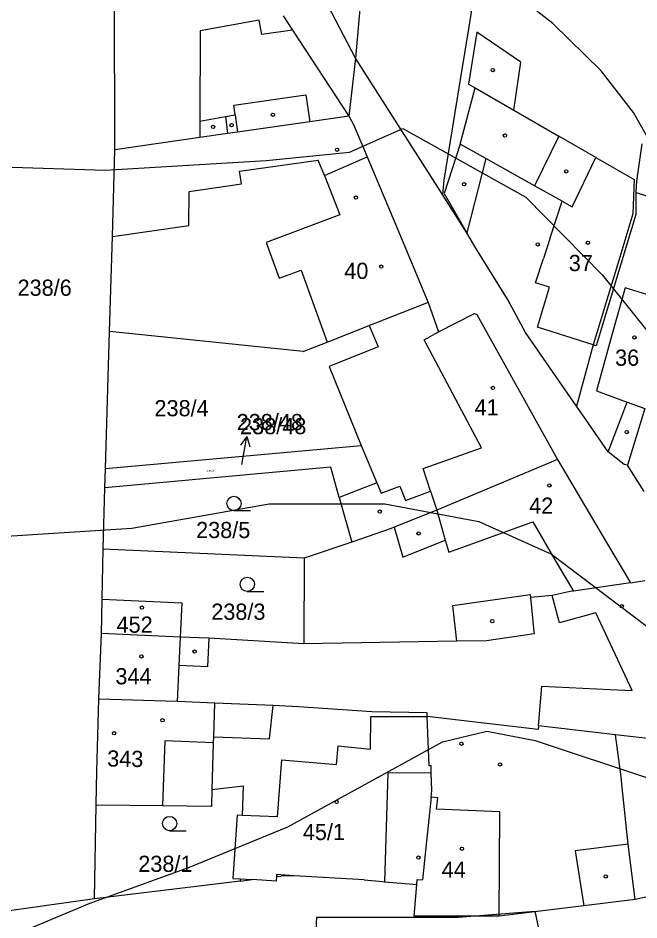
# Model space of a CAD drawing. Extents: x -555860 to -552701, y -1187050 to -1182291.
# Drawn here: x -554496.6 to -554431.4, y -1184380.5 to -1184285.9 of the extents above; entities that cross this region are included whole.
import ezdxf

# ---------------------------------------------------------------- set-up
doc = ezdxf.new("R2010")
doc.units = 0
for name, color, linetype in [('CYKLISTI_stav', 7, 'Continuous'), ('LEG_2b', 7, 'Continuous'), ('Level 16', 7, 'Continuous'), ('Level 25', 7, 'Continuous'), ('Level 40', 7, 'Continuous'), ('Level 41', 7, 'Continuous'), ('navrh_BV', 7, 'Continuous'), ('stav_BV', 7, 'Continuous')]:
    doc.layers.add(name, color=color, linetype=linetype)

msp = doc.modelspace()

# ---------------------------------------------------------------- linework, layer by layer
at = {"layer": 'CYKLISTI_stav'}
for p, q in [((-554471.28, -1184286.15), (-554477.48, -1184287.27)), ((-554471.01, -1184287.65), (-554471.28, -1184286.15)), ((-554477.48, -1184287.27), (-554477.49, -1184296.75)), ((-554467.77, -1184287.2), (-554471.01, -1184287.65)), ((-554448.44, -1184287.41), (-554449.31, -1184292.87)), ((-554443.8, -1184290.55), (-554448.44, -1184287.41)), ((-554444.56, -1184295.6), (-554443.8, -1184290.55)), ((-554449.31, -1184292.87), (-554448.62, -1184293.26)), ((-554473.94, -1184295.08), (-554466.36, -1184293.99)), ((-554466.36, -1184293.99), (-554465.96, -1184296.81)), ((-554450.19, -1184299.16), (-554448.62, -1184293.26)), ((-554448.62, -1184293.26), (-554444.56, -1184295.6)), ((-554473.79, -1184296.07), (-554473.94, -1184295.08)), ((-554474.79, -1184296.25), (-554473.79, -1184296.07)), ((-554473.79, -1184296.07), (-554473.53, -1184297.9)), ((-554444.56, -1184295.6), (-554439.82, -1184298.33)), ((-554477.49, -1184296.75), (-554474.79, -1184296.25)), ((-554477.49, -1184296.75), (-554477.49, -1184298.47)), ((-554474.79, -1184296.25), (-554474.58, -1184298.05)), ((-554439.82, -1184298.33), (-554442.36, -1184303.54)), ((-554435.93, -1184300.57), (-554439.82, -1184298.33)), ((-554450.19, -1184299.16), (-554451.87, -1184304.34)), ((-554447.5, -1184300.67), (-554450.19, -1184299.16)), ((-554464.43, -1184302.46), (-554459.94, -1184300.5)), ((-554447.5, -1184300.67), (-554449.49, -1184308.45)), ((-554442.36, -1184303.54), (-554447.5, -1184300.67)), ((-554438.44, -1184305.74), (-554435.93, -1184300.57)), ((-554435.93, -1184300.57), (-554431.91, -1184302.88)), ((-554464.43, -1184302.46), (-554465.07, -1184300.83)), ((-554439.48, -1184305.15), (-554442.36, -1184303.54)), ((-554431.91, -1184302.88), (-554432.05, -1184306.45)), ((-554451.87, -1184304.34), (-554449.49, -1184308.45)), ((-554440.74, -1184309), (-554439.48, -1184305.15)), ((-554439.48, -1184305.15), (-554438.44, -1184305.74)), ((-554432.05, -1184306.45), (-554433.43, -1184311.02)), ((-554440.74, -1184309), (-554441.44, -1184311.15)), ((-554442.26, -1184313.69), (-554441.44, -1184311.15)), ((-554433.43, -1184311.02), (-554436.21, -1184320.22)), ((-554440.81, -1184314.16), (-554442.26, -1184313.69)), ((-554442.07, -1184318.34), (-554440.81, -1184314.16)), ((-554432.86, -1184314.23), (-554434.23, -1184319.07)), ((-554427.82, -1184315.79), (-554432.86, -1184314.23)), ((-554436.21, -1184320.22), (-554442.07, -1184318.34)), ((-554453.94, -1184319.7), (-554452.44, -1184318.85)), ((-554447.95, -1184331.01), (-554453.94, -1184319.7)), ((-554434.23, -1184319.07), (-554435.88, -1184325.02)), ((-554435.88, -1184325.02), (-554432.65, -1184326.21)), ((-554434.64, -1184331.45), (-554432.65, -1184326.21)), ((-554432.65, -1184326.21), (-554430.81, -1184326.89)), ((-554454.06, -1184333.19), (-554447.95, -1184331.01)), ((-554453.29, -1184335.57), (-554454.06, -1184333.19)), ((-554458.92, -1184334.68), (-554458.46, -1184335.77)), ((-554458.46, -1184335.77), (-554456.51, -1184335.02)), ((-554456.51, -1184335.02), (-554455.93, -1184336.54)), ((-554455.93, -1184336.54), (-554453.29, -1184335.57)), ((-554453.29, -1184335.57), (-554452.64, -1184337.57)), ((-554452.64, -1184337.57), (-554451.74, -1184340.71)), ((-554457.09, -1184339.35), (-554456.2, -1184342.49)), ((-554451.38, -1184341.97), (-554442.56, -1184338.79)), ((-554442.56, -1184338.79), (-554440.23, -1184342.76)), ((-554456.2, -1184342.49), (-554451.74, -1184340.71)), ((-554451.74, -1184340.71), (-554451.38, -1184341.97)), ((-554440.23, -1184342.76), (-554438.3, -1184346.04)), ((-554450.96, -1184347.57), (-554442.84, -1184346.41)), ((-554442.84, -1184346.41), (-554442.81, -1184346.73)), ((-554439.76, -1184349.39), (-554440.52, -1184346.51)), ((-554450.54, -1184351.28), (-554450.96, -1184347.57)), ((-554435.93, -1184348.32), (-554439.76, -1184349.39)), ((-554434.63, -1184351.09), (-554435.93, -1184348.32)), ((-554479.55, -1184350.86), (-554479.69, -1184353.84)), ((-554432.13, -1184356.46), (-554434.63, -1184351.09)), ((-554441.97, -1184360.18), (-554441.61, -1184356.03)), ((-554441.61, -1184356.03), (-554434.44, -1184356.35)), ((-554434.44, -1184356.35), (-554432.13, -1184356.46)), ((-554470.2, -1184361.56), (-554469.81, -1184358.06)), ((-554459.55, -1184359.2), (-554453.65, -1184359.21)), ((-554476.03, -1184361.35), (-554470.2, -1184361.56)), ((-554481.18, -1184361.76), (-554481.4, -1184368.55)), ((-554476.05, -1184361.96), (-554481.18, -1184361.76)), ((-554469.35, -1184369.71), (-554468.88, -1184363.76)), ((-554457.77, -1184365.12), (-554458.13, -1184376.53)), ((-554457.77, -1184365.12), (-554453.21, -1184365.09)), ((-554452.53, -1184367.72), (-554453.23, -1184367.65)), ((-554452.66, -1184368.91), (-554452.53, -1184367.72)), ((-554446.02, -1184369.2), (-554452.66, -1184368.91)), ((-554469.35, -1184369.71), (-554473.05, -1184369.57)), ((-554446.1, -1184380.14), (-554446.02, -1184369.2)), ((-554432.55, -1184372.58), (-554438.11, -1184373.31)), ((-554438.11, -1184373.31), (-554437.2, -1184379.05)), ((-554473.26, -1184376.23), (-554472, -1184376.31))]:
    msp.add_line(p, q, dxfattribs=at)
for points in [[(-554486.68, -1184308.84), (-554478.67, -1184307.68), (-554478.61, -1184304.12), (-554473.14, -1184303.33), (-554473.33, -1184302), (-554465.07, -1184300.83)], [(-554464.43, -1184302.46), (-554462.81, -1184306.58), (-554470.54, -1184309.47), (-554469.19, -1184313.22), (-554466.88, -1184312.39), (-554464.14, -1184319.92)], [(-554468.88, -1184363.76), (-554463.15, -1184364.25), (-554462.98, -1184362.28), (-554459.6, -1184362.63), (-554459.55, -1184359.2)], [(-554467.63, -1184375.9), (-554469.46, -1184375.76), (-554469.47, -1184376)]]:
    msp.add_lwpolyline(points, dxfattribs=at)
at = {"layer": 'Level 16'}
for p, q in [((-554472.558, -1184329.826), (-554473.228, -1184330.722)), ((-554473.09, -1184332.779), (-554472.558, -1184329.826)), ((-554472.558, -1184329.826), (-554472.243, -1184330.899))]:
    msp.add_line(p, q, dxfattribs=at)
at = {"layer": 'Level 25'}
for p, q in [((-554473.922, -1184337.6), (-554472.172, -1184337.6)), ((-554472.522, -1184346.08), (-554470.772, -1184346.08)), ((-554480.672, -1184371.18), (-554478.922, -1184371.18))]:
    msp.add_line(p, q, dxfattribs=at)
for centre, radius in [((-554446.767, -1184291.389), 0.175), ((-554469.827, -1184296.069), 0.175), ((-554474.167, -1184297.149), 0.175), ((-554476.107, -1184297.349), 0.175), ((-554445.477, -1184298.259), 0.175), ((-554463.097, -1184299.749), 0.175), ((-554439.037, -1184302.009), 0.175), ((-554449.767, -1184303.369), 0.175), ((-554461.117, -1184304.759), 0.175), ((-554436.767, -1184309.499), 0.175), ((-554442.037, -1184309.669), 0.175), ((-554458.457, -1184311.999), 0.175), ((-554431.897, -1184319.429), 0.175), ((-554446.737, -1184324.729), 0.175), ((-554432.697, -1184329.359), 0.175), ((-554440.807, -1184334.949), 0.175), ((-554473.922, -1184336.85), 0.75), ((-554458.617, -1184337.699), 0.175), ((-554454.547, -1184339.999), 0.175), ((-554472.522, -1184345.33), 0.75), ((-554483.577, -1184347.779), 0.175), ((-554433.227, -1184347.629), 0.175), ((-554446.817, -1184349.199), 0.175), ((-554483.627, -1184352.889), 0.175), ((-554478.057, -1184352.389), 0.175), ((-554481.417, -1184359.599), 0.175), ((-554486.507, -1184360.959), 0.175), ((-554450.047, -1184362.059), 0.175), ((-554445.997, -1184364.219), 0.175), ((-554463.147, -1184368.169), 0.175), ((-554480.672, -1184370.43), 0.75), ((-554449.987, -1184373.079), 0.175), ((-554454.557, -1184374.009), 0.175), ((-554434.897, -1184375.969), 0.175)]:
    msp.add_circle(centre, radius, dxfattribs=at)
at = {"layer": 'Level 40'}
msp.add_lwpolyline([(-554517.787, -1184390.832), (-554489.12, -1184378.802), (-554478.588, -1184374.99), (-554468.255, -1184370.76), (-554452.027, -1184361.871), (-554447.37, -1184360.74), (-554442.29, -1184361.728), (-554418.197, -1184369.738), (-554409.458, -1184366.376), (-554396.338, -1184363.41), (-554380.817, -1184362.722), (-554365.423, -1184363.422), (-554347.817, -1184363.408), (-554330.133, -1184359.878), (-554319.19, -1184353.342), (-554303.762, -1184342.476), (-554293.19, -1184332.553), (-554285.468, -1184327.774)], dxfattribs=at)
at = {"layer": 'Level 41'}
for points in [[(-554293.988, -1184268.716), (-554293.412, -1184281.01), (-554294.964, -1184300.484), (-554298.492, -1184313.749), (-554303.996, -1184324.052), (-554309.076, -1184329.836), (-554316.414, -1184335.34), (-554324.881, -1184337.598), (-554333.348, -1184337.456), (-554340.404, -1184336.47), (-554371.45, -1184329.836), (-554394.028, -1184326.874), (-554403.906, -1184324.475), (-554409.551, -1184322.216), (-554417.453, -1184316.854), (-554422.533, -1184311.492), (-554425.356, -1184307.54), (-554431.988, -1184295.828), (-554435.375, -1184291.453), (-554440.455, -1184286.513), (-554452.732, -1184276.919), (-554465.01, -1184266.053), (-554485.983, -1184245.539), (-554497.733, -1184248.25)], [(-554497.187, -1184301.561), (-554487.447, -1184301.896), (-554470.521, -1184300.888), (-554461.782, -1184299.992), (-554456.18, -1184297.527), (-554443.277, -1184304.718), (-554435.234, -1184312.904), (-554426.061, -1184324.334), (-554416.042, -1184332.094), (-554407.011, -1184336.893), (-554400.237, -1184339.432), (-554388.948, -1184342.538), (-554357.338, -1184345.641), (-554338.872, -1184346.657), (-554323.635, -1184345.314), (-554313.551, -1184341.055), (-554305.26, -1184335.453), (-554299.21, -1184330.076), (-554292.935, -1184321.785), (-554278.313, -1184297.803)], [(-554498.307, -1184340.326), (-554484.625, -1184339.433), (-554470.231, -1184336.893), (-554458.095, -1184336.893), (-554448.217, -1184338.726), (-554440.606, -1184342.176), (-554427.833, -1184351.812), (-554420.886, -1184348.45), (-554411.251, -1184350.242), (-554403.58, -1184350.68), (-554376.674, -1184353.773), (-554345.212, -1184355.026), (-554329.432, -1184353.226), (-554307.277, -1184342.401), (-554296.788, -1184332.229)], [(-554465.587, -1184387.182), (-554465.231, -1184380.243), (-554450.389, -1184380.254), (-554442.35, -1184379.631), (-554441.049, -1184385.742)]]:
    msp.add_lwpolyline(points, dxfattribs=at)
at = {"layer": 'navrh_BV'}
for p, q in [((-554461.16, -1184290.15), (-554471.93, -1184269.33)), ((-554459.52, -1184271.8), (-554461.16, -1184290.15)), ((-554486.41, -1184299.76), (-554486.48, -1184276.68)), ((-554447.92, -1184278.57), (-554449.27, -1184286.85)), ((-554468.76, -1184285.7), (-554467.77, -1184287.2)), ((-554467.77, -1184287.2), (-554461.85, -1184296.22)), ((-554449.27, -1184286.85), (-554450.17, -1184292.38)), ((-554461.16, -1184290.15), (-554461.85, -1184296.22)), ((-554452.02, -1184304.43), (-554461.16, -1184290.15)), ((-554450.31, -1184293.25), (-554451.89, -1184302.93)), ((-554450.17, -1184292.38), (-554450.31, -1184293.25)), ((-554465.96, -1184296.81), (-554473.53, -1184297.9)), ((-554461.85, -1184296.22), (-554465.96, -1184296.81)), ((-554461.85, -1184296.22), (-554461.37, -1184297.1)), ((-554473.53, -1184297.9), (-554474.58, -1184298.05)), ((-554461.37, -1184297.1), (-554459.94, -1184300.5)), ((-554477.49, -1184298.47), (-554486.41, -1184299.76)), ((-554474.58, -1184298.05), (-554477.49, -1184298.47)), ((-554486.68, -1184308.84), (-554486.41, -1184299.76)), ((-554431.11, -1184299.13), (-554431.66, -1184303.03)), ((-554459.94, -1184300.5), (-554456.98, -1184307.56)), ((-554451.89, -1184302.93), (-554452.02, -1184304.43)), ((-554431.66, -1184303.03), (-554431.75, -1184304.22)), ((-554449.49, -1184308.45), (-554452.02, -1184304.43)), ((-554431.75, -1184304.22), (-554431.76, -1184306.54)), ((-554431.75, -1184304.22), (-554425.65, -1184306.07)), ((-554431.76, -1184306.54), (-554435.92, -1184320.31)), ((-554456.98, -1184307.56), (-554453.52, -1184315.77)), ((-554486.97, -1184318.81), (-554486.68, -1184308.84)), ((-554448.55, -1184310.07), (-554449.49, -1184308.45)), ((-554445.21, -1184315.42), (-554448.55, -1184310.07)), ((-554453.52, -1184315.77), (-554459.08, -1184317.93)), ((-554453.52, -1184315.77), (-554452.44, -1184318.85)), ((-554443.31, -1184318.91), (-554445.21, -1184315.42)), ((-554452.44, -1184318.85), (-554448.67, -1184316.93)), ((-554448.67, -1184316.93), (-554448.42, -1184317.03)), ((-554448.42, -1184317.03), (-554439.96, -1184332.25)), ((-554464.14, -1184319.92), (-554459.73, -1184318.19)), ((-554459.08, -1184317.93), (-554459.73, -1184318.19)), ((-554459.73, -1184318.19), (-554458.78, -1184320.41)), ((-554487.4, -1184333.2), (-554486.97, -1184318.81)), ((-554466.67, -1184320.91), (-554486.97, -1184318.81)), ((-554437.96, -1184326.65), (-554443.31, -1184318.91)), ((-554466.67, -1184320.91), (-554464.14, -1184319.92)), ((-554458.78, -1184320.41), (-554463.94, -1184322.48)), ((-554436.21, -1184320.22), (-554437.96, -1184326.65)), ((-554435.92, -1184320.31), (-554436.21, -1184320.22)), ((-554463.94, -1184322.48), (-554460.57, -1184330.76)), ((-554437, -1184328.03), (-554437.96, -1184326.65)), ((-554430.81, -1184326.89), (-554432.63, -1184332.84)), ((-554434.64, -1184331.45), (-554437, -1184328.03)), ((-554487.4, -1184333.2), (-554460.57, -1184330.76)), ((-554460.57, -1184330.76), (-554458.92, -1184334.68)), ((-554432.98, -1184332.78), (-554434.64, -1184331.45)), ((-554439.96, -1184332.25), (-554452.64, -1184337.57)), ((-554439.96, -1184332.25), (-554435.38, -1184339.99)), ((-554432.63, -1184332.84), (-554432.98, -1184332.78)), ((-554430.88, -1184335.61), (-554432.63, -1184332.84)), ((-554463.75, -1184333.06), (-554487.47, -1184335.21)), ((-554487.47, -1184335.21), (-554487.4, -1184333.2)), ((-554462.86, -1184336.24), (-554463.75, -1184333.06)), ((-554458.92, -1184334.68), (-554462.86, -1184336.24)), ((-554487.66, -1184341.66), (-554487.47, -1184335.21)), ((-554462.86, -1184336.24), (-554461.56, -1184340.9)), ((-554452.64, -1184337.57), (-554457.09, -1184339.35)), ((-554457.41, -1184339.46), (-554461.56, -1184340.9)), ((-554457.09, -1184339.35), (-554457.41, -1184339.46)), ((-554435.38, -1184339.99), (-554432.3, -1184345.19)), ((-554461.56, -1184340.9), (-554466.54, -1184342.59)), ((-554487.76, -1184346.89), (-554487.66, -1184341.66)), ((-554466.54, -1184342.59), (-554487.66, -1184341.66)), ((-554466.54, -1184342.59), (-554466.57, -1184351.58)), ((-554432.3, -1184345.19), (-554438.3, -1184346.04)), ((-554432.3, -1184345.19), (-554430.81, -1184344.94)), ((-554438.65, -1184346.09), (-554440.52, -1184346.51)), ((-554438.3, -1184346.04), (-554438.65, -1184346.09)), ((-554487.83, -1184350.5), (-554487.76, -1184346.89)), ((-554487.76, -1184346.89), (-554479.39, -1184347.28)), ((-554440.52, -1184346.51), (-554442.81, -1184346.73)), ((-554442.81, -1184346.73), (-554442.44, -1184350.33)), ((-554479.39, -1184347.28), (-554479.55, -1184350.86)), ((-554488.1, -1184357.39), (-554487.83, -1184350.5)), ((-554479.55, -1184350.86), (-554487.83, -1184350.5)), ((-554476.56, -1184350.99), (-554479.55, -1184350.86)), ((-554442.42, -1184350.53), (-554447.4, -1184351.26)), ((-554442.44, -1184350.33), (-554442.42, -1184350.53)), ((-554476.56, -1184350.99), (-554476.7, -1184353.98)), ((-554466.57, -1184351.58), (-554476.56, -1184350.99)), ((-554450.54, -1184351.28), (-554466.57, -1184351.58)), ((-554447.4, -1184351.26), (-554450.54, -1184351.28)), ((-554479.69, -1184353.84), (-554479.87, -1184357.64)), ((-554476.7, -1184353.98), (-554479.69, -1184353.84)), ((-554488.31, -1184364.92), (-554488.1, -1184357.39)), ((-554479.87, -1184357.64), (-554488.1, -1184357.39)), ((-554475.92, -1184357.8), (-554479.87, -1184357.64)), ((-554476.03, -1184361.35), (-554475.92, -1184357.8)), ((-554469.81, -1184358.06), (-554475.92, -1184357.8)), ((-554467.16, -1184358.17), (-554469.81, -1184358.06)), ((-554459.44, -1184358.71), (-554467.16, -1184358.17)), ((-554453.65, -1184358.81), (-554459.44, -1184358.71)), ((-554453.65, -1184359.21), (-554453.65, -1184358.81)), ((-554453.43, -1184364.36), (-554453.65, -1184359.21)), ((-554446.77, -1184360.01), (-554453.65, -1184359.21)), ((-554441.99, -1184360.55), (-554446.77, -1184360.01)), ((-554441.97, -1184360.18), (-554441.99, -1184360.55)), ((-554433.86, -1184361.13), (-554441.97, -1184360.18)), ((-554476.05, -1184361.96), (-554476.03, -1184361.35)), ((-554429.56, -1184361.63), (-554433.86, -1184361.13)), ((-554433.28, -1184365.54), (-554433.86, -1184361.13)), ((-554476.19, -1184366.87), (-554476.05, -1184361.96)), ((-554488.37, -1184368.46), (-554488.31, -1184364.92)), ((-554453.23, -1184364.37), (-554453.43, -1184364.36)), ((-554453.21, -1184365.09), (-554453.23, -1184364.37)), ((-554453.15, -1184366.95), (-554453.21, -1184365.09)), ((-554433.16, -1184366.65), (-554433.28, -1184365.54)), ((-554476.24, -1184368.59), (-554476.19, -1184366.87)), ((-554476.19, -1184366.87), (-554472.95, -1184366.47)), ((-554472.95, -1184366.47), (-554473.05, -1184369.57)), ((-554453.23, -1184367.65), (-554453.15, -1184366.95)), ((-554432.55, -1184372.58), (-554433.16, -1184366.65)), ((-554453.23, -1184367.65), (-554453.71, -1184372.28)), ((-554488.55, -1184378.33), (-554488.37, -1184368.46)), ((-554488.37, -1184368.46), (-554481.4, -1184368.55)), ((-554481.4, -1184368.55), (-554476.24, -1184368.59)), ((-554473.59, -1184369.55), (-554474.04, -1184376.18)), ((-554473.05, -1184369.57), (-554473.59, -1184369.55)), ((-554453.71, -1184372.28), (-554454.14, -1184376.35)), ((-554431.83, -1184378.41), (-554432.55, -1184372.58)), ((-554473.27, -1184376.46), (-554488.55, -1184378.33)), ((-554474.04, -1184376.18), (-554473.26, -1184376.23)), ((-554473.26, -1184376.23), (-554473.27, -1184376.46)), ((-554473.27, -1184376.46), (-554472, -1184376.31)), ((-554469.5, -1184376.46), (-554472, -1184376.31)), ((-554469.47, -1184376), (-554469.5, -1184376.46)), ((-554469.47, -1184376), (-554468.98, -1184375.94)), ((-554467.63, -1184375.9), (-554468.98, -1184375.94)), ((-554460.26, -1184376.34), (-554467.63, -1184375.9)), ((-554460.26, -1184376.34), (-554458.3, -1184376.52)), ((-554454.73, -1184376.84), (-554454.68, -1184376.31)), ((-554454.68, -1184376.31), (-554454.14, -1184376.35)), ((-554458.3, -1184376.52), (-554458.13, -1184376.53)), ((-554458.13, -1184376.53), (-554455.95, -1184376.73)), ((-554455.95, -1184376.73), (-554454.73, -1184376.84)), ((-554455.02, -1184380.16), (-554454.73, -1184376.84)), ((-554425.47, -1184377.02), (-554431.83, -1184378.41)), ((-554488.55, -1184378.33), (-554500.4, -1184379.99)), ((-554431.83, -1184378.41), (-554437.2, -1184379.05)), ((-554437.2, -1184379.05), (-554446.1, -1184380.14)), ((-554446.1, -1184380.14), (-554455.02, -1184380.16))]:
    msp.add_line(p, q, dxfattribs=at)
at = {"layer": 'stav_BV'}
for p, q in [((-554472.569, -1184329.825), (-554473.236, -1184330.724)), ((-554473.09, -1184332.78), (-554472.569, -1184329.825)), ((-554472.569, -1184329.825), (-554472.25, -1184330.898))]:
    msp.add_line(p, q, dxfattribs=at)

# ---------------------------------------------------------------- texts
at = {"layer": 'LEG_2b'}
for s, p in [('37', (-554438.78, -1184312.475)), ('40', (-554462.34, -1184313.295)), ('238/6', (-554496.63, -1184315.065)), ('36', (-554433.92, -1184322.405)), ('238/4', (-554482.26, -1184327.705)), ('41', (-554448.66, -1184327.615)), ('238/48', (-554473.276, -1184329.585)), ('42', (-554442.94, -1184337.935)), ('238/5', (-554477.89, -1184340.485)), ('238/3', (-554476.3, -1184349.055)), ('452', (-554486.24, -1184350.415)), ('344', (-554486.36, -1184355.825)), ('45/1', (-554466.69, -1184372.165)), ('238/1', (-554483.96, -1184375.505)), ('44', (-554452.12, -1184376.115))]:
    msp.add_text(s, height=1.7, dxfattribs=at).set_placement(p)
for s, height, rotation, p in [('238/48', 0.2, 4, (-554476.786, -1184333.549)), ('343', 1.7, 359, (-554487.237, -1184364.444))]:
    msp.add_text(s, height=height, rotation=rotation, dxfattribs=at).set_placement(p)
at = {"layer": 'Level 16'}
msp.add_text('238/48', height=1.7, dxfattribs=at).set_placement((-554473.631, -1184329.16))

doc.saveas('drawing.dxf')
